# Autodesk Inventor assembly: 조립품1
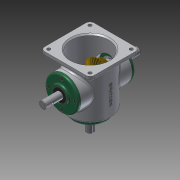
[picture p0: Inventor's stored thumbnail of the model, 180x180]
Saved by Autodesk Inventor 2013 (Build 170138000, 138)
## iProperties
Created: 2015-10
Part Number: 조립품1
Document SubType Name: Assembly
Designer: Administrator
Author: Administrator
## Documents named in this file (14)
- C:\Users\Administrator\Desktop\451008V1026\조립품1.iam
- C:\Users\Administrator\Desktop\451008V1026\부품1.ipt
- C:\Users\Administrator\Desktop\451008V1026\서브 축.ipt
- 서브 축.ipt
- C:\Users\Administrator\Desktop\451008V1026\오일실.ipt
- C:\Users\Administrator\Desktop\451008V1026\커버.ipt
- C:\Users\Administrator\Desktop\451008V1026\키 4x4.ipt
- C:\Users\Administrator\Desktop\451008V1026\키 5x5.ipt
- C:\Users\Administrator\Desktop\451008V1026\M4.ipt
- C:\Users\Administrator\Desktop\451008V1026\메인 베벨기어.ipt
- C:\Users\Administrator\Desktop\451008V1026\메인 축.ipt
- 메인 축.ipt
- C:\Users\Administrator\Desktop\451008V1026\베어링 6203.ipt
- C:\Users\Administrator\Desktop\451008V1026\서브 베벨기어.ipt
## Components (12 placed, 1 different names)
1. M4:1
2. M4:2
3. M4:3
4. M4:4
5. M4:5
6. M4:6
7. M4:7
8. M4:8
9. M4:9
10. M4:10
11. M4:11
12. M4:12
